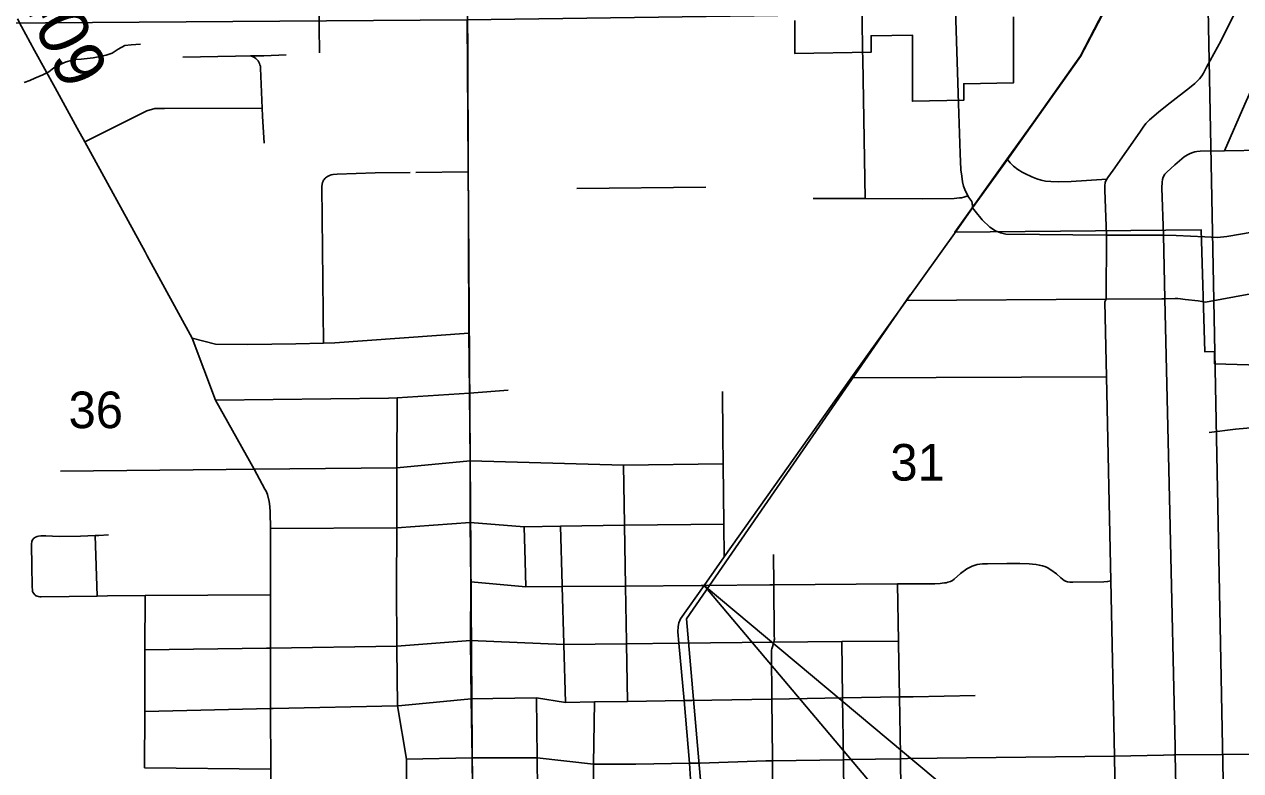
# Model space of a CAD drawing. Extents: x 0 to 34, y 0 to 22.
# Drawn here: x 5.027 to 6.418, y 17.402 to 18.256 of the extents above; entities that cross this region are included whole.
import ezdxf

# ---------------------------------------------------------------- set-up
doc = ezdxf.new("R2010")
doc.units = 0
for name, color, linetype in [('GM_X_City_Street', 7, 'Continuous'), ('GM_X_Corporation', 7, 'Continuous'), ('GM_X_County_Road', 7, 'Continuous'), ('GM_X_County_Road_Text', 7, 'Continuous'), ('GM_X_Minor_River', 7, 'Continuous'), ('GM_X_Rail_Line', 7, 'Continuous'), ('GM_X_Section', 7, 'Continuous'), ('GM_X_Section_Text', 7, 'Continuous'), ('GM_X_State_Route', 7, 'Continuous'), ('GM_X_Township_Road', 7, 'Continuous'), ('SH_Text', 7, 'Continuous')]:
    doc.layers.add(name, color=color, linetype=linetype)

msp = doc.modelspace()

# ---------------------------------------------------------------- linework, layer by layer
at = {"layer": 'GM_X_City_Street'}
for p, q in [((5.3641, 18.2238), (5.3633, 18.2834)), ((5.4745, 18.0868), (5.5342, 18.0878)), ((6.2639, 17.9421), (6.2644, 18.0151)), ((5.9723, 17.8517), (6.2643, 17.8532)), ((5.5358, 17.8344), (5.5799, 17.8376)), ((5.1098, 17.6022), (5.1077, 17.6713)), ((5.1641, 17.4054), (5.3084, 17.4042)), ((5.4638, 17.4154), (5.5388, 17.4169))]:
    msp.add_line(p, q, dxfattribs=at)
for points in [[(5.2078, 18.2188), (5.2681, 18.2201), (5.2852, 18.2203), (5.3004, 18.2205), (5.3262, 18.2217)], [(5.301, 18.1203), (5.2991, 18.1515), (5.2987, 18.1604), (5.2968, 18.2064), (5.2966, 18.2084), (5.2961, 18.2102), (5.2956, 18.2117), (5.2948, 18.2131), (5.2939, 18.2145), (5.2928, 18.2158), (5.2913, 18.2172), (5.2897, 18.2184), (5.2876, 18.2195), (5.2852, 18.2203)], [(5.0959, 18.122), (5.1452, 18.1469), (5.1667, 18.1573), (5.176, 18.16), (5.1868, 18.16), (5.2987, 18.1604)], [(5.371, 18.0807), (5.3721, 18.0816), (5.3732, 18.0823), (5.3755, 18.0835), (5.3775, 18.0841), (5.3797, 18.0846), (5.3846, 18.085), (5.4278, 18.0864), (5.4681, 18.0867)], [(5.3687, 17.8917), (5.367, 18.0707), (5.3671, 18.0736), (5.3677, 18.0755), (5.3683, 18.0771), (5.3689, 18.0782), (5.3695, 18.079), (5.3703, 18.08), (5.371, 18.0807)], [(6.3372, 17.6817), (6.3313, 17.9424), (6.3297, 18.015)], [(6.2639, 17.9421), (6.3278, 17.9424), (6.3313, 17.9424), (6.3428, 17.9426), (6.3459, 17.9425), (6.3489, 17.9422), (6.3542, 17.9417), (6.3691, 17.9399), (6.3778, 17.9385)], [(5.2187, 17.8971), (5.2454, 17.8903), (5.2822, 17.8901), (5.3372, 17.8909), (5.3687, 17.8917), (5.3816, 17.892), (5.5351, 17.9031)], [(5.827, 17.647), (5.8267, 17.6846), (5.826, 17.7533), (5.8257, 17.7857), (5.8252, 17.8362)], [(5.2454, 17.8264), (5.4432, 17.8287), (5.453, 17.829), (5.5358, 17.8344)], [(5.4635, 17.3427), (5.4638, 17.4154), (5.4533, 17.4767), (5.4528, 17.5426), (5.4528, 17.5447), (5.4522, 17.6127), (5.4525, 17.6801), (5.4525, 17.6808), (5.4527, 17.749), (5.4527, 17.75), (5.453, 17.829)], [(6.3818, 17.7893), (6.4121, 17.7932), (6.4337, 17.795), (6.442, 17.7948), (6.4466, 17.7945), (6.4493, 17.7926), (6.452, 17.7896), (6.457, 17.7824), (6.4612, 17.7776), (6.4647, 17.775), (6.4689, 17.7731), (6.4746, 17.7713), (6.483, 17.7703), (6.5122, 17.7673), (6.532, 17.7665), (6.5456, 17.7671)], [(5.068, 17.7449), (5.2575, 17.7469), (5.2893, 17.7472), (5.4527, 17.749), (5.5364, 17.7569)], [(5.5364, 17.7569), (5.7118, 17.752), (5.826, 17.7533)], [(5.7166, 17.4816), (5.7154, 17.5476), (5.7154, 17.5492), (5.7142, 17.6136), (5.713, 17.6831), (5.713, 17.6844), (5.7118, 17.752)], [(5.308, 17.6793), (5.4525, 17.6801), (5.5367, 17.6863)], [(5.5367, 17.6863), (5.5985, 17.6815), (5.6399, 17.6821), (5.713, 17.6831), (5.8267, 17.6846)], [(5.0372, 17.6681), (5.0382, 17.6689), (5.0395, 17.6696), (5.0412, 17.6704), (5.0429, 17.6708), (5.0453, 17.6709), (5.0475, 17.671), (5.0513, 17.6709), (5.0664, 17.6704), (5.091, 17.6708), (5.1077, 17.6713), (5.1119, 17.6715), (5.1229, 17.6724)], [(5.6002, 17.6127), (5.5995, 17.642), (5.5985, 17.6815)], [(5.6456, 17.4804), (5.6437, 17.5469), (5.6437, 17.5476), (5.6419, 17.6131), (5.6418, 17.6149), (5.6399, 17.6821)], [(6.3428, 17.4295), (6.3372, 17.6807), (6.3372, 17.6817)], [(5.0392, 17.6028), (5.0385, 17.6035), (5.0373, 17.6051), (5.0365, 17.6065), (5.0361, 17.6075), (5.036, 17.6085), (5.0357, 17.613), (5.035, 17.6369), (5.0347, 17.6608), (5.0347, 17.6623), (5.035, 17.6639), (5.0353, 17.6651), (5.0358, 17.6661), (5.0364, 17.6672), (5.0372, 17.6681)], [(5.8843, 17.2611), (5.8824, 17.4022), (5.8823, 17.4136), (5.8823, 17.4168), (5.8817, 17.4843), (5.8813, 17.5375), (5.8813, 17.5391), (5.8814, 17.5404), (5.8817, 17.5417), (5.882, 17.5428), (5.8834, 17.5477), (5.8839, 17.5493), (5.8842, 17.5505), (5.8844, 17.5516), (5.8845, 17.5528), (5.8844, 17.5573), (5.8839, 17.6149), (5.8835, 17.6496)], [(6.08, 17.6173), (6.0811, 17.6174), (6.0829, 17.6179), (6.0858, 17.6188), (6.0882, 17.62), (6.0903, 17.6216), (6.0974, 17.6278), (6.1045, 17.6332), (6.1106, 17.6363), (6.1166, 17.6381), (6.1226, 17.6389), (6.1284, 17.6392), (6.1504, 17.6396), (6.1651, 17.6394), (6.1759, 17.639), (6.1796, 17.6387), (6.1839, 17.6382), (6.1875, 17.6376), (6.1911, 17.6368), (6.194, 17.6359), (6.1965, 17.6348), (6.2009, 17.6323), (6.2071, 17.6275), (6.2121, 17.623), (6.2159, 17.62), (6.2174, 17.6191), (6.2197, 17.6183), (6.2225, 17.618), (6.2258, 17.6179), (6.2612, 17.6184), (6.2656, 17.6188), (6.2692, 17.6197)], [(5.5372, 17.6185), (5.6002, 17.6127), (5.6419, 17.6131), (5.7142, 17.6136), (5.8007, 17.6143), (5.8041, 17.6143), (5.8793, 17.6149), (5.8839, 17.6149), (6.0255, 17.616), (6.066, 17.6163), (6.068, 17.6163), (6.0741, 17.6166), (6.0763, 17.6168), (6.079, 17.6171), (6.08, 17.6173)], [(6.031, 17.264), (6.0297, 17.3452), (6.0286, 17.416), (6.0286, 17.4204), (6.0275, 17.4867), (6.0266, 17.5475), (6.0265, 17.5507), (6.0255, 17.616)], [(5.0392, 17.6028), (5.04, 17.6024), (5.0413, 17.6019), (5.0427, 17.6016), (5.0443, 17.6013), (5.0458, 17.6012), (5.1098, 17.6022), (5.1216, 17.6024), (5.1648, 17.6027), (5.3082, 17.6037)], [(5.1641, 17.4054), (5.1643, 17.4701), (5.1646, 17.5408), (5.1648, 17.6027)], [(5.1646, 17.5408), (5.3037, 17.5427), (5.3083, 17.5427), (5.4528, 17.5447), (5.5371, 17.5514)], [(5.5371, 17.5514), (5.6437, 17.5469), (5.7154, 17.5476), (5.7752, 17.5482), (5.8839, 17.5493), (5.9615, 17.5501), (6.0265, 17.5507)], [(5.9658, 17.2627), (5.9636, 17.4064), (5.9635, 17.4149), (5.9625, 17.4857), (5.9615, 17.5501)], [(5.1643, 17.4701), (5.3083, 17.4734), (5.3113, 17.4735), (5.4533, 17.4767), (5.4582, 17.4769), (5.5378, 17.4844)], [(5.5378, 17.4844), (5.6124, 17.4855), (5.6456, 17.4804), (5.6787, 17.481), (5.7166, 17.4816), (5.7812, 17.4827), (5.7901, 17.4828), (5.8817, 17.4843), (5.9625, 17.4857), (6.0275, 17.4867), (6.0432, 17.487), (6.1141, 17.4882)], [(5.6139, 17.3439), (5.6132, 17.4171), (5.6124, 17.4855)], [(5.677, 17.3382), (5.6772, 17.3549), (5.6778, 17.4096), (5.6787, 17.481)], [(6.3464, 17.2701), (6.3446, 17.3491), (6.343, 17.4203), (6.343, 17.4229), (6.3428, 17.4295)]]:
    msp.add_lwpolyline(points, dxfattribs=at)
at = {"layer": 'GM_X_Corporation'}
for points in [[(6.2664, 18.2814), (6.2346, 18.2202), (6.1811, 18.145), (6.1508, 18.1025), (6.0909, 18.0184), (6.3727, 18.0212), (6.3768, 17.8818), (6.3881, 17.882), (6.3881, 17.8678), (6.5688, 17.8625)], [(5.908, 18.2608), (5.908, 18.2229), (5.9951, 18.2245), (5.9951, 18.2434), (6.0424, 18.2442), (6.0424, 18.1685), (6.1012, 18.1695), (6.1012, 18.1884), (6.158, 18.1894), (6.158, 18.2652)]]:
    msp.add_lwpolyline(points, dxfattribs=at)
at = {"layer": 'GM_X_County_Road'}
msp.add_line((6.0358, 17.9404), (6.2639, 17.9421), dxfattribs=at)
for points in [[(5.5346, 18.0161), (5.5345, 18.0439), (5.5342, 18.0878), (5.5337, 18.2301), (5.533, 18.2948), (5.5315, 18.4336), (5.528, 18.7847)], [(5.1647, 17.9959), (5.0959, 18.122), (5.0871, 18.1376), (5.0618, 18.1836), (5.0383, 18.2266), (5.0235, 18.2541), (5.0188, 18.2628)], [(5.5425, 17.2636), (5.5405, 17.3429), (5.5388, 17.4169), (5.5378, 17.4844), (5.5371, 17.5514), (5.5372, 17.6185), (5.5367, 17.6863), (5.5364, 17.7569), (5.5358, 17.8344), (5.5351, 17.9031), (5.5346, 18.0161)], [(5.2187, 17.8971), (5.1671, 17.9914), (5.1647, 17.9959)], [(6.2734, 17.4188), (6.2692, 17.6197), (6.2643, 17.8532), (6.2625, 17.9387), (6.2639, 17.9421)], [(5.3087, 17.2528), (5.3085, 17.3346), (5.3084, 17.3966), (5.3084, 17.4042), (5.3083, 17.4734), (5.3083, 17.5427), (5.3083, 17.5764), (5.3082, 17.6037), (5.308, 17.6793), (5.3079, 17.6981), (5.3074, 17.7045), (5.3066, 17.7102), (5.3046, 17.7183), (5.3031, 17.722), (5.3018, 17.7246), (5.2893, 17.7472), (5.2454, 17.8264), (5.2187, 17.8971)], [(5.5388, 17.4169), (5.6132, 17.4171), (5.6778, 17.4096), (5.726, 17.4099), (5.7873, 17.4109), (5.7995, 17.4111), (5.8747, 17.4134), (5.8823, 17.4136), (5.9635, 17.4149), (5.9716, 17.415), (6.0286, 17.416), (6.0367, 17.4161), (6.2734, 17.4188), (6.3296, 17.4201), (6.3413, 17.4203), (6.343, 17.4203)], [(6.28, 16.8817), (6.2793, 16.939), (6.2783, 17.0104), (6.2778, 17.0424), (6.2761, 17.1306), (6.2761, 17.1826), (6.2762, 17.2688), (6.2747, 17.3471), (6.2734, 17.4188)], [(6.343, 17.4203), (6.397, 17.4208), (6.4973, 17.4217), (6.5065, 17.4217), (6.5156, 17.4217)]]:
    msp.add_lwpolyline(points, dxfattribs=at)
at = {"layer": 'GM_X_Minor_River'}
msp.add_lwpolyline([(5.1594, 18.2336), (5.1488, 18.233), (5.1417, 18.2321), (5.1338, 18.2281), (5.1271, 18.2234), (5.1203, 18.221), (5.1131, 18.2197), (5.1052, 18.218), (5.0916, 18.2166), (5.0852, 18.2161), (5.0803, 18.2152), (5.0746, 18.2135), (5.0682, 18.2107), (5.0604, 18.2068), (5.0548, 18.2021), (5.0477, 18.1985), (5.0387, 18.1949), (5.033, 18.1921), (5.0263, 18.19)], dxfattribs=at)
at = {"layer": 'GM_X_Rail_Line'}
msp.add_lwpolyline([(5.8309, 17.1868), (5.8105, 17.2685), (5.7839, 17.5759), (6.0398, 17.9469)], dxfattribs=at)
at = {"layer": 'GM_X_Section'}
for points in [[(5.5332, 18.2617), (6.3807, 18.2734), (6.4001, 17.2736), (5.5401, 17.2602)], [(4.5147, 18.2545), (5.5332, 18.2617), (5.5401, 17.2602), (4.5299, 17.2417)]]:
    msp.add_lwpolyline(points, close=True, dxfattribs=at)
at = {"layer": 'GM_X_State_Route'}
for points in [[(6.0924, 18.0198), (6.1113, 18.0463), (6.151, 18.1019), (6.2348, 18.2196), (6.2666, 18.2808)], [(5.9838, 17.8679), (6.0358, 17.9404), (6.0924, 18.0198)], [(5.7921, 17.3377), (5.7873, 17.4109), (5.7812, 17.4827), (5.7752, 17.5482), (5.7741, 17.5612), (5.7743, 17.5673), (5.7754, 17.5715), (5.7772, 17.5761), (5.8041, 17.6143), (5.827, 17.647), (5.9723, 17.8517), (5.9838, 17.8679)]]:
    msp.add_lwpolyline(points, dxfattribs=at)
at = {"layer": 'GM_X_Township_Road'}
for p, q in [((5.9883, 18.0571), (5.9855, 18.216)), ((5.6586, 18.0684), (5.8062, 18.0701)), ((6.2644, 18.0151), (6.3297, 18.015))]:
    msp.add_line(p, q, dxfattribs=at)
for points in [[(5.9855, 18.216), (5.9853, 18.2269), (5.9844, 18.2959), (5.9842, 18.3163)], [(6.095, 18.1659), (6.0919, 18.2613), (6.0901, 18.3119)], [(6.2644, 18.0151), (6.2626, 18.0665), (6.2625, 18.0729), (6.2627, 18.0743), (6.263, 18.0754), (6.2638, 18.0774), (6.2649, 18.0794), (6.2661, 18.0813), (6.272, 18.0894), (6.3024, 18.1331), (6.3062, 18.1389), (6.3094, 18.1431), (6.3136, 18.1471), (6.3184, 18.1512), (6.3244, 18.1563), (6.3371, 18.1667), (6.3595, 18.1838), (6.3655, 18.1888), (6.3706, 18.194), (6.3733, 18.1975), (6.3752, 18.2007), (6.3789, 18.2076), (6.3954, 18.2378), (6.4145, 18.2763)], [(6.3993, 18.1116), (6.4227, 18.1651), (6.438, 18.1991), (6.4425, 18.2079), (6.4452, 18.2119), (6.4479, 18.2148), (6.4509, 18.2175), (6.454, 18.22), (6.4568, 18.2218), (6.46, 18.2233), (6.4641, 18.2248), (6.4679, 18.2257), (6.4725, 18.2267), (6.4762, 18.227), (6.4824, 18.2274), (6.488, 18.2276)], [(6.1056, 18.0601), (6.1024, 18.0673), (6.1009, 18.0714), (6.0996, 18.0763), (6.0988, 18.0828), (6.0979, 18.0899), (6.0969, 18.1085), (6.095, 18.1659)], [(6.151, 18.1019), (6.1543, 18.0981), (6.158, 18.0943), (6.163, 18.0903), (6.1679, 18.0874), (6.171, 18.0857), (6.179, 18.0818), (6.1848, 18.0796), (6.1897, 18.0782), (6.1946, 18.0771), (6.2007, 18.0765), (6.2098, 18.0762), (6.2238, 18.0765), (6.2649, 18.0794)], [(6.3297, 18.015), (6.3276, 18.0694), (6.328, 18.0757), (6.3285, 18.0787), (6.3293, 18.0816), (6.3312, 18.0848), (6.3334, 18.0874), (6.3424, 18.0955), (6.3532, 18.1048), (6.3569, 18.1071), (6.3602, 18.1087), (6.3633, 18.1099), (6.3656, 18.1104), (6.3677, 18.1108), (6.3716, 18.1111), (6.3993, 18.1116), (6.4439, 18.1123), (6.4889, 18.1134)], [(5.9288, 18.0572), (5.9739, 18.0572), (5.9883, 18.0571), (6.0538, 18.0566), (6.0901, 18.0572), (6.0931, 18.0574), (6.0961, 18.0577), (6.0986, 18.058), (6.1011, 18.0585), (6.1036, 18.0593), (6.1056, 18.0601), (6.1071, 18.0581), (6.1102, 18.0537), (6.1105, 18.0531), (6.1107, 18.0524), (6.1109, 18.0509), (6.111, 18.0499), (6.1113, 18.0463)], [(6.1113, 18.0463), (6.1142, 18.0425), (6.1223, 18.0327), (6.1311, 18.0245), (6.1376, 18.02), (6.143, 18.0178), (6.1491, 18.0164), (6.2644, 18.0151)], [(6.3297, 18.015), (6.3441, 18.0148), (6.3768, 18.0134), (6.3914, 18.0126), (6.4019, 18.0138), (6.4309, 18.0185), (6.4399, 18.02)], [(6.3778, 17.9385), (6.4293, 17.9481), (6.4373, 17.9494)]]:
    msp.add_lwpolyline(points, dxfattribs=at)
at = {"layer": 'SH_Text'}
msp.add_lwpolyline([(5.8041, 17.6143), (7.0506, 16.5706), (7.0506, 16.1356)], close=True, dxfattribs=at)

# ---------------------------------------------------------------- texts
at = {"layer": 'GM_X_County_Road_Text'}
msp.add_text('C-409', height=0.05682, rotation=294.895, dxfattribs=at).set_placement((4.9856, 18.3668))
at = {"layer": 'GM_X_Section_Text'}
for s, p in [('36', (5.0772, 17.7943)), ('31', (6.0172, 17.7343))]:
    msp.add_text(s, height=0.04186, rotation=0, dxfattribs=at).set_placement(p)

doc.saveas('drawing.dxf')
